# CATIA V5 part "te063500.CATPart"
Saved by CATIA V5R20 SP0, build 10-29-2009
Part number: 1
Definition: NONE
Nomenclature: 1
Source: Unknown
Description: PART-1-DESC
Bounding box of the stored display mesh (mm): x 0 to 500, y -3 to 3, z -2.853 to 2.853
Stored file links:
  C:\Users\Utente\Desktop\IO LAVORO\3D X SITO CF\CUMSA\3D files TE\te063500.CATPart
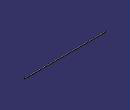
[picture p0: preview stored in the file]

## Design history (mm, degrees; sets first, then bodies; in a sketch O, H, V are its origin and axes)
Body1 "1" (main body)
  Solid1: solid without history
